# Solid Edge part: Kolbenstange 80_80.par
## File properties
Username: ahadarics
Dokumentum tartalom típus: 0
Author: ahadarics
Last saved by: ahadarics
Revision: 81
Sűrűség: 0,000 kg/m^3
Pontosság: 0,990
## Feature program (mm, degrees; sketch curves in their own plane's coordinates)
base feature "unnamed BaseFeature 1"
thread "unnamed Thread 1"
chamfer "Letörés_1"  SetBackValue2 = 20 deg
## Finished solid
Body 1: solid body, 19 faces, 27 edges, 11 vertices.
  Faces by surface: plane 8, cylinder 5, cone 3, torus 3
  Edges by curve: circle 15, line 7, curve on surface 3, ellipse 2
Bounding box of the edges (mm; curved faces can reach further): 80.000 x 80.000 x 254.000, from (-40, -40, -79.5) to (40, 40, 174.5).
Cylindrical faces by radius (mm): R8.75 x1, R10 x1, R12.25 x1, R12.5 x1, R40 x1
Conical faces (half-angle, radius in mm at the cone's reference point): 20 deg R10 x1, 30 deg R12.375 x1, 60 deg R9.375 x1
Toroidal faces (ring radius, tube radius in mm): R9.15 r0.4 x2, R10.45 r1.8 x1
Planar faces by outward normal: +x 1, +z 3, -x 1, -z 1, oblique 2
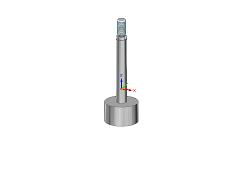
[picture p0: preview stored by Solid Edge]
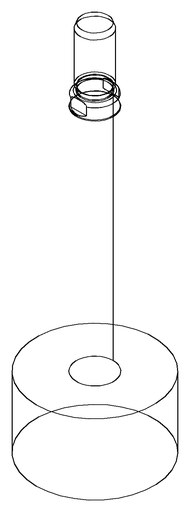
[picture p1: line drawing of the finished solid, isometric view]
